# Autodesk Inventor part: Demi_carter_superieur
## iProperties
Shininess: 64.0
Length Units: 11269
Angle Units: 11279
Time Units: 11290
Mass Units: 11283
Length Display Precision: 3
Angle Display Precision: 2
Compacted: True
Part Number: Demi_carter_superieur
Document SubType Name: Sheet Metal
Created: 2008-02
Material: Acier doux
Designer: Pascal
Density: 0.0
Volumn: 0.0
Area: 0.0
PropertySet Name: Model Information
Control State: 0
Master: False
Checked Out: False
DESIGNATION: Demi carter supérieur
OBSERVATIONS: Tôle ep 15/10
MATIERE_PIECE: X2CrNi 18-11
Author: Pascal
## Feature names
1. Plaque1
2. Pli1
3. Ouverture1
